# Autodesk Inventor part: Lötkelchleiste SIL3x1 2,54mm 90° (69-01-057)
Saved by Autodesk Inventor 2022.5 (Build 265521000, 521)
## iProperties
Created: 2024-12
Part Number: Lötkelchleiste SIL3x1 2,54mm 90° (69-01-057)
Material: Generic
Document SubType Name: Modeling
Designer: AdminForWorker
Density: 1 g/cm^3
Appearance: Default
Title: Lötkelchleiste SIL3x1 2,54mm 90° (69-01-057)
Author: AdminForWorker
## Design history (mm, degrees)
feature "Body1"
body "Solid1"
